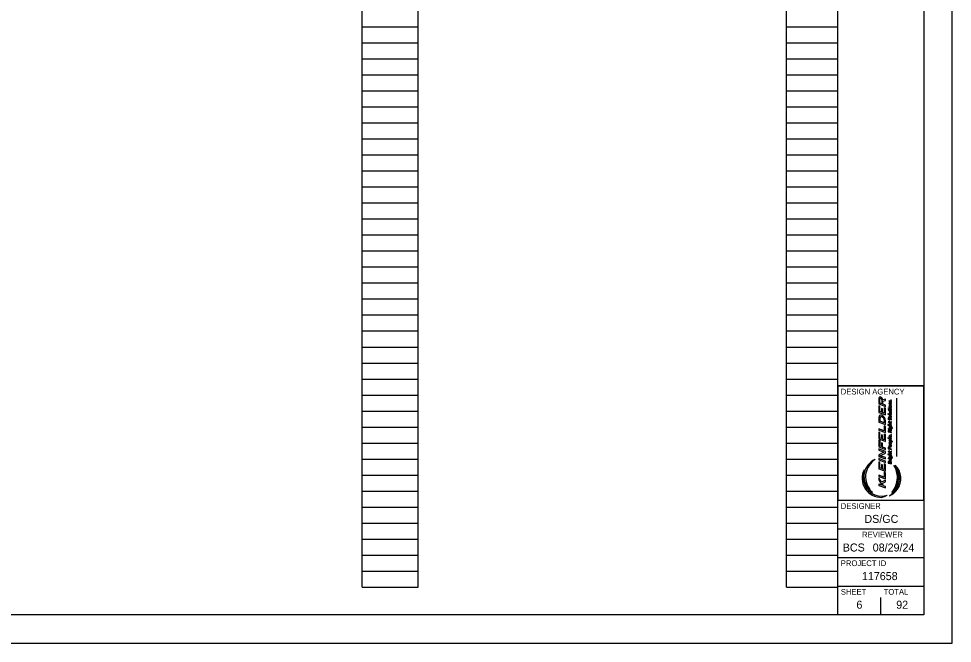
# Model space of a CAD drawing. Extents: x -9.5 to 34, y -6.8 to 28.4.
# Drawn here: x 17.67 to 34, y 0 to 10.92 of the extents above; entities that cross this region are included whole.
import ezdxf

# ---------------------------------------------------------------- set-up
doc = ezdxf.new("R2010")
doc.units = 0
for name, color, linetype in [('PV_P_Drive', 7, 'Continuous'), ('SH_Border', 7, 'Continuous'), ('SH_Cut_Line', 7, 'Continuous'), ('SH_Data', 7, 'Continuous'), ('SH_Text', 7, 'Continuous')]:
    doc.layers.add(name, color=color, linetype=linetype)

msp = doc.modelspace()

# ---------------------------------------------------------------- linework, layer by layer
at = {"layer": 'PV_P_Drive'}
for p, q in [((23.68, 0.98), (23.68, 21.14)), ((24.66, 0.98), (24.66, 21.14)), ((31.1, 0.98), (31.1, 21.14)), ((32, 0.98), (32, 21.14)), ((23.68, 10.78), (24.66, 10.78)), ((31.1, 10.78), (32, 10.78)), ((23.68, 10.5), (24.66, 10.5)), ((31.1, 10.5), (32, 10.5)), ((23.68, 10.22), (24.66, 10.22)), ((31.1, 10.22), (32, 10.22)), ((23.68, 9.94), (24.66, 9.94)), ((31.1, 9.94), (32, 9.94)), ((23.68, 9.66), (24.66, 9.66)), ((31.1, 9.66), (32, 9.66)), ((23.68, 9.38), (24.66, 9.38)), ((31.1, 9.38), (32, 9.38)), ((23.68, 9.1), (24.66, 9.1)), ((31.1, 9.1), (32, 9.1)), ((23.68, 8.82), (24.66, 8.82)), ((31.1, 8.82), (32, 8.82)), ((23.68, 8.54), (24.66, 8.54)), ((31.1, 8.54), (32, 8.54)), ((23.68, 8.26), (24.66, 8.26)), ((31.1, 8.26), (32, 8.26)), ((23.68, 7.98), (24.66, 7.98)), ((31.1, 7.98), (32, 7.98)), ((23.68, 7.7), (24.66, 7.7)), ((31.1, 7.7), (32, 7.7)), ((23.68, 7.42), (24.66, 7.42)), ((31.1, 7.42), (32, 7.42)), ((23.68, 7.14), (24.66, 7.14)), ((31.1, 7.14), (32, 7.14)), ((23.68, 6.86), (24.66, 6.86)), ((31.1, 6.86), (32, 6.86)), ((23.68, 6.58), (24.66, 6.58)), ((31.1, 6.58), (32, 6.58)), ((23.68, 6.3), (24.66, 6.3)), ((31.1, 6.3), (32, 6.3)), ((23.68, 6.02), (24.66, 6.02)), ((31.1, 6.02), (32, 6.02)), ((23.68, 5.74), (24.66, 5.74)), ((31.1, 5.74), (32, 5.74)), ((23.68, 5.46), (24.66, 5.46)), ((31.1, 5.46), (32, 5.46)), ((23.68, 5.18), (24.66, 5.18)), ((31.1, 5.18), (32, 5.18)), ((23.68, 4.9), (24.66, 4.9)), ((31.1, 4.9), (32, 4.9)), ((23.68, 4.62), (24.66, 4.62)), ((31.1, 4.62), (32, 4.62)), ((23.68, 4.34), (24.66, 4.34)), ((31.1, 4.34), (32, 4.34)), ((23.68, 4.06), (24.66, 4.06)), ((31.1, 4.06), (32, 4.06)), ((23.68, 3.78), (24.66, 3.78)), ((31.1, 3.78), (32, 3.78)), ((23.68, 3.5), (24.66, 3.5)), ((31.1, 3.5), (32, 3.5)), ((23.68, 3.22), (24.66, 3.22)), ((31.1, 3.22), (32, 3.22)), ((23.68, 2.94), (24.66, 2.94)), ((31.1, 2.94), (32, 2.94)), ((23.68, 2.66), (24.66, 2.66)), ((31.1, 2.66), (32, 2.66)), ((23.68, 2.38), (24.66, 2.38)), ((31.1, 2.38), (32, 2.38)), ((23.68, 2.1), (24.66, 2.1)), ((31.1, 2.1), (32, 2.1)), ((23.68, 1.82), (24.66, 1.82)), ((31.1, 1.82), (32, 1.82)), ((23.68, 1.54), (24.66, 1.54)), ((31.1, 1.54), (32, 1.54)), ((23.68, 1.26), (24.66, 1.26)), ((31.1, 1.26), (32, 1.26)), ((23.68, 0.98), (24.66, 0.98)), ((31.1, 0.98), (32, 0.98))]:
    msp.add_line(p, q, dxfattribs=at)
msp.add_lwpolyline([(32, 2.5), (33.5, 2.5), (33.5, 4.5), (32, 4.5)], close=True, dxfattribs=at)
at = {"layer": 'SH_Border'}
msp.add_lwpolyline([(0, 0), (34, 0), (34, 22), (0, 22)], close=True, dxfattribs=at)
at = {"layer": 'SH_Cut_Line'}
for p, q in [((32, 0.5), (32, 21.5)), ((32, 4.5), (33.5, 4.5)), ((32, 2.5), (33.5, 2.5)), ((32, 2), (33.5, 2)), ((32, 1.5), (33.5, 1.5)), ((32, 1), (33.5, 1))]:
    msp.add_line(p, q, dxfattribs=at)
msp.add_lwpolyline([(1.5, 21.5), (33.5, 21.5), (33.5, 0.5), (1.5, 0.5)], close=True, dxfattribs=at)
at = {"layer": 'SH_Data'}
for p, q in [((32.75, 3.5), (32.75, 3.5)), ((32.375, 0.675), (32.375, 0.675)), ((32.75, 0.5), (32.75, 0.8))]:
    msp.add_line(p, q, dxfattribs=at)
at = {"layer": 'SH_Text'}
for p, q in [((32.735, 4.201), (32.735, 4.271)), ((32.901, 4.239), (32.895, 4.241)), ((32.925, 4.077), (32.9, 4.082)), ((32.927, 4.212), (32.933, 4.21)), ((32.934, 4.086), (32.928, 4.087)), ((32.888, 3.94), (32.88, 3.942)), ((32.936, 3.789), (32.893, 3.798)), ((32.924, 3.905), (32.932, 3.903)), ((32.934, 3.873), (32.928, 3.875)), ((32.942, 3.755), (32.949, 3.753)), ((32.902, 3.709), (32.902, 3.699)), ((32.91, 3.626), (32.91, 3.606)), ((32.933, 3.627), (32.926, 3.629)), ((32.91, 3.463), (32.91, 3.442)), ((32.933, 3.464), (32.926, 3.465)), ((32.936, 3.273), (32.893, 3.282)), ((32.905, 3.41), (32.905, 3.403)), ((32.912, 3.402), (32.912, 3.412)), ((32.934, 3.358), (32.928, 3.359)), ((32.903, 3.161), (32.903, 3.152)), ((32.928, 3.157), (32.928, 3.147)), ((32.942, 3.239), (32.949, 3.237))]:
    msp.add_line(p, q, dxfattribs=at)
for points in [[(32.715, 4.286), (32.715, 4.187), (32.829, 4.143), (32.829, 4.165), (32.787, 4.181), (32.787, 4.232), (32.829, 4.243), (32.829, 4.269), (32.786, 4.259)], [(32.766, 4.257), (32.766, 4.189), (32.735, 4.201)], [(32.926, 4.255), (32.926, 4.247), (32.934, 4.245), (32.934, 4.253), (32.926, 4.255)], [(33.024, 4.283), (33.024, 3.267)], [(32.715, 4.154), (32.715, 4.035), (32.829, 3.992), (32.829, 4.111), (32.809, 4.119), (32.809, 4.023), (32.78, 4.034), (32.78, 4.099), (32.759, 4.107), (32.759, 4.042), (32.735, 4.051), (32.735, 4.147), (32.715, 4.154)], [(32.877, 4.114), (32.877, 4.106), (32.885, 4.104), (32.885, 4.113), (32.877, 4.114)], [(32.9, 4.082), (32.9, 4.093), (32.893, 4.094), (32.893, 4.083), (32.881, 4.086), (32.884, 4.078), (32.893, 4.076), (32.893, 4.067), (32.9, 4.065), (32.9, 4.074), (32.924, 4.069)], [(32.899, 4.179), (32.893, 4.18), (32.893, 4.173), (32.934, 4.164), (32.934, 4.172), (32.911, 4.177)], [(32.893, 4.111), (32.893, 4.103), (32.934, 4.094), (32.934, 4.102), (32.893, 4.111)], [(32.906, 4.199), (32.934, 4.193), (32.934, 4.201), (32.909, 4.207)], [(32.715, 3.948), (32.715, 3.867), (32.829, 3.824), (32.829, 3.897)], [(32.808, 3.906), (32.808, 3.855), (32.736, 3.882), (32.736, 3.942)], [(32.875, 4.013), (32.875, 4.005), (32.934, 3.993), (32.934, 4.001), (32.875, 4.013)], [(32.928, 4.044), (32.934, 4.043), (32.934, 4.05), (32.893, 4.059), (32.893, 4.051), (32.917, 4.046)], [(32.921, 4.024), (32.893, 4.03), (32.893, 4.022), (32.918, 4.017)], [(32.715, 3.752), (32.715, 3.728), (32.829, 3.685), (32.829, 3.793), (32.809, 3.801), (32.809, 3.717), (32.715, 3.752)], [(32.898, 3.818), (32.874, 3.823), (32.874, 3.815), (32.934, 3.802), (32.934, 3.81), (32.913, 3.815)], [(32.893, 3.882), (32.893, 3.871), (32.881, 3.874), (32.884, 3.865), (32.893, 3.863), (32.893, 3.854), (32.9, 3.853), (32.9, 3.862), (32.924, 3.857)], [(32.925, 3.864), (32.9, 3.87), (32.9, 3.881), (32.893, 3.882)], [(32.893, 3.798), (32.893, 3.79), (32.9, 3.789)], [(32.908, 3.836), (32.934, 3.831), (32.934, 3.839), (32.908, 3.844)], [(32.759, 3.644), (32.759, 3.579), (32.735, 3.588), (32.735, 3.683), (32.715, 3.691), (32.715, 3.572), (32.829, 3.529), (32.829, 3.648), (32.809, 3.656), (32.809, 3.56), (32.78, 3.571), (32.78, 3.636), (32.759, 3.644)], [(32.875, 3.595), (32.875, 3.587), (32.934, 3.574), (32.934, 3.582), (32.875, 3.595)], [(32.877, 3.753), (32.877, 3.745), (32.885, 3.743), (32.885, 3.751), (32.877, 3.753)], [(32.879, 3.716), (32.879, 3.696), (32.934, 3.684), (32.934, 3.692), (32.909, 3.698), (32.909, 3.705)], [(32.902, 3.699), (32.885, 3.703), (32.885, 3.711)], [(32.893, 3.749), (32.893, 3.741), (32.934, 3.732), (32.934, 3.741), (32.893, 3.749)], [(32.914, 3.711), (32.934, 3.716), (32.934, 3.724), (32.911, 3.717)], [(32.92, 3.605), (32.916, 3.605), (32.916, 3.634), (32.913, 3.634)], [(32.926, 3.65), (32.926, 3.642), (32.934, 3.64), (32.934, 3.648), (32.926, 3.65)], [(32.759, 3.504), (32.759, 3.439), (32.736, 3.448), (32.736, 3.544), (32.715, 3.552), (32.715, 3.433), (32.829, 3.389), (32.829, 3.413), (32.78, 3.431), (32.78, 3.497), (32.759, 3.504)], [(32.899, 3.538), (32.893, 3.539), (32.893, 3.532), (32.951, 3.52), (32.951, 3.528), (32.929, 3.533)], [(32.92, 3.441), (32.916, 3.441), (32.916, 3.47), (32.913, 3.471)], [(32.715, 3.295), (32.715, 3.267), (32.829, 3.223), (32.829, 3.247), (32.741, 3.28), (32.829, 3.327), (32.829, 3.355), (32.715, 3.399), (32.715, 3.375), (32.802, 3.341), (32.715, 3.295)], [(32.898, 3.302), (32.874, 3.307), (32.874, 3.299), (32.934, 3.286), (32.934, 3.294), (32.913, 3.299)], [(32.879, 3.418), (32.879, 3.4), (32.934, 3.389), (32.934, 3.397), (32.912, 3.402)], [(32.893, 3.366), (32.893, 3.355), (32.881, 3.358), (32.884, 3.349), (32.893, 3.348), (32.893, 3.338), (32.9, 3.337), (32.9, 3.346), (32.924, 3.341)], [(32.905, 3.403), (32.885, 3.407), (32.885, 3.414)], [(32.925, 3.348), (32.9, 3.354), (32.9, 3.365), (32.893, 3.366)], [(32.893, 3.282), (32.893, 3.274), (32.9, 3.273)], [(32.908, 3.321), (32.934, 3.315), (32.934, 3.323), (32.908, 3.328)], [(32.715, 3.229), (32.715, 3.206), (32.829, 3.162), (32.829, 3.185), (32.715, 3.229)], [(32.715, 3.172), (32.715, 3.053), (32.829, 3.009), (32.829, 3.128), (32.809, 3.136), (32.809, 3.041), (32.78, 3.052), (32.78, 3.116), (32.759, 3.124), (32.759, 3.059), (32.735, 3.068), (32.735, 3.164), (32.715, 3.172)], [(32.877, 3.237), (32.877, 3.229), (32.885, 3.227), (32.885, 3.235), (32.877, 3.237)], [(32.879, 3.168), (32.879, 3.149), (32.934, 3.137), (32.934, 3.16)], [(32.903, 3.152), (32.885, 3.156), (32.885, 3.164)], [(32.893, 3.233), (32.893, 3.225), (32.934, 3.216), (32.934, 3.225), (32.893, 3.233)], [(32.9, 3.215), (32.893, 3.216), (32.893, 3.209)], [(32.899, 3.2), (32.893, 3.201), (32.893, 3.193), (32.934, 3.185), (32.934, 3.192), (32.911, 3.197)], [(32.928, 3.147), (32.909, 3.151), (32.909, 3.16)], [(32.715, 2.941), (32.715, 2.917), (32.829, 2.874), (32.829, 2.982), (32.809, 2.99), (32.809, 2.906), (32.715, 2.941)], [(32.715, 2.895), (32.715, 2.859), (32.769, 2.765), (32.715, 2.785), (32.715, 2.761), (32.829, 2.718), (32.829, 2.742), (32.795, 2.755), (32.772, 2.794), (32.829, 2.824), (32.829, 2.853), (32.76, 2.816), (32.715, 2.895)]]:
    msp.add_lwpolyline(points, dxfattribs=at)
for centre, radius, start, end in [((32.738, 4.285), 0.0235, 105.8602, 175.9527), ((32.734, 4.272), 0.0359, 63.9111, 93.4134), ((32.746, 4.272), 0.0116, 120.9282, 182.8587), ((32.744, 4.27), 0.0128, 71.295, 106.2465), ((32.739, 4.256), 0.0278, 3.188, 69.9483), ((32.728, 4.249), 0.059, 10.1322, 68.6534), ((32.907, 4.193), 0.0143, 136.2913, 182.0825), ((32.908, 4.192), 0.0157, 176.9051, 236.2062), ((32.916, 4.231), 0.0237, 155.8068, 177.518), ((32.909, 4.23), 0.0164, 172.9331, 212.9177), ((32.913, 4.141), 0.0207, 134.8616, 186.3333), ((32.914, 4.14), 0.0218, 183.0085, 235.1138), ((32.904, 4.225), 0.0102, 205.2791, 253.4117), ((32.906, 4.191), 0.0157, 78.3727, 128.7252), ((32.908, 4.231), 0.0105, 131.8722, 213.0859), ((32.909, 4.192), 0.0107, 164.3628, 217.5642), ((32.908, 4.141), 0.00982, 114.8029, 183.3912), ((32.91, 4.14), 0.0115, 178.7964, 222.8298), ((32.905, 4.191), 0.00751, 82.4034, 156.5016), ((32.911, 4.135), 0.0236, 80.4774, 121.3769), ((32.904, 4.228), 0.00472, 212.4264, 286.081), ((32.916, 4.196), 0.0192, 214.0093, 253.9548), ((32.917, 4.147), 0.0212, 222.6118, 267.8201), ((32.904, 4.225), 0.0096, 252.4577, 305.4949), ((32.915, 4.14), 0.0225, 234.7204, 275.0527), ((32.911, 4.134), 0.0176, 73.9781, 113.6531), ((32.9, 4.234), 0.0117, 294.6007, 337.5251), ((32.899, 4.232), 0.018, 306.3564, 329.8219), ((32.924, 4.224), 0.0139, 114.5985, 155.8852), ((32.937, 4.21), 0.0248, 133.1465, 150.3389), ((32.913, 4.137), 0.0217, 48.9189, 86.1506), ((32.911, 4.131), 0.0201, 30.777, 75.0314), ((32.918, 4.138), 0.0124, 261.6619, 324.7522), ((32.919, 4.134), 0.0164, 263.7465, 315.576), ((32.923, 4.224), 0.013, 67.7239, 111.621), ((32.923, 4.225), 0.00487, 54.9774, 133.6656), ((32.921, 4.222), 0.0081, 0.828, 56.4407), ((32.914, 4.221), 0.0154, 324.4952, 5.8801), ((32.919, 4.223), 0.0157, 25.7964, 57.936), ((32.917, 4.139), 0.0181, 359.1065, 54.0048), ((32.917, 4.136), 0.0122, 333.802, 26.7946), ((32.918, 4.081), 0.012, 359.8271, 33.4272), ((32.916, 4.135), 0.0192, 318.3025, 9.3316), ((32.917, 4.222), 0.0183, 351.4651, 24.96), ((32.894, 4.224), 0.0413, 341.1844, 354.3531), ((32.914, 4.081), 0.0207, 339.7319, 13.8876), ((32.763, 3.948), 0.0481, 135.8191, 179.4263), ((32.749, 3.952), 0.0358, 73.1779, 125.9306), ((32.756, 3.942), 0.0203, 112.5545, 180.292), ((32.755, 3.943), 0.0192, 70.7496, 111.8258), ((32.736, 3.898), 0.0911, 25.2799, 75.3517), ((32.747, 3.901), 0.0624, 24.8644, 76.4065), ((32.763, 3.907), 0.0458, 358.9317, 26.1463), ((32.744, 3.896), 0.0851, 0.5101, 28.8607), ((32.902, 3.931), 0.0246, 153.0923, 182.7278), ((32.914, 3.931), 0.0359, 182.7278, 201.3007), ((32.894, 3.926), 0.0157, 207.7495, 253.8409), ((32.899, 3.93), 0.0144, 140.4782, 179.939), ((32.897, 3.929), 0.0124, 175.3728, 230.5265), ((32.893, 3.928), 0.00909, 239.5135, 284.896), ((32.913, 3.969), 0.0207, 134.8616, 186.3333), ((32.914, 3.967), 0.0218, 183.0085, 235.1138), ((32.888, 3.932), 0.0149, 299.565, 339.2556), ((32.908, 3.969), 0.00982, 114.8029, 183.3912), ((32.91, 3.968), 0.0115, 178.7964, 222.8298), ((32.911, 3.963), 0.0236, 80.4774, 121.3769), ((32.887, 3.931), 0.0238, 303.1236, 337.1341), ((32.917, 3.974), 0.0212, 222.6118, 267.8201), ((32.915, 3.968), 0.0225, 234.7204, 275.0527), ((32.921, 3.918), 0.0202, 112.5492, 156.2929), ((32.911, 3.961), 0.0176, 73.9781, 113.6531), ((32.919, 3.918), 0.011, 90.8577, 158.2517), ((32.918, 3.92), 0.018, 58.4507, 105.0331), ((32.913, 3.965), 0.0217, 48.9189, 86.1506), ((32.911, 3.959), 0.0201, 30.777, 75.0314), ((32.918, 3.966), 0.0124, 261.6619, 324.7522), ((32.911, 4.028), 0.0192, 34.0093, 73.9548), ((32.919, 3.962), 0.0164, 263.7465, 315.576), ((32.922, 4.032), 0.0157, 258.3727, 308.7252), ((32.918, 3.919), 0.0099, 7.9705, 84.8943), ((32.922, 4.032), 0.00751, 262.4034, 336.5016), ((32.926, 4.078), 0.00899, 258.837, 329.2244), ((32.909, 3.917), 0.0192, 321.116, 10.1848), ((32.926, 4.081), 0.00406, 265.2766, 359.8271), ((32.919, 4.032), 0.0107, 344.3628, 37.5642), ((32.915, 3.919), 0.0199, 358.5943, 53.7031), ((32.92, 4.031), 0.0157, 356.9051, 56.2062), ((32.917, 3.966), 0.0181, 359.1065, 54.0048), ((32.917, 3.964), 0.0122, 333.802, 26.7946), ((32.916, 3.963), 0.0192, 318.3025, 9.3316), ((32.921, 4.03), 0.0143, 316.2913, 2.0825), ((32.903, 3.918), 0.0327, 332.8538, 1.7076), ((32.893, 3.926), 0.0158, 256.3758, 294.8902), ((32.909, 3.83), 0.017, 145.2436, 189.7855), ((32.912, 3.776), 0.0195, 166.4234, 246.8498), ((32.905, 3.829), 0.0129, 185.2859, 235.9293), ((32.904, 3.778), 0.0113, 111.6426, 168.888), ((32.906, 3.83), 0.0141, 80.6828, 137.5266), ((32.907, 3.828), 0.00818, 136.5529, 210.7681), ((32.909, 3.777), 0.0102, 156.145, 220.58), ((32.909, 3.776), 0.0105, 93.2154, 153.4686), ((32.917, 3.835), 0.0202, 210.678, 259.5619), ((32.906, 3.829), 0.00748, 78.1668, 139.4713), ((32.917, 3.786), 0.0229, 224.9845, 280.2941), ((32.916, 3.782), 0.0268, 243.1201, 290.541), ((32.91, 3.764), 0.0226, 65.4895, 96.081), ((32.916, 3.773), 0.0125, 4.6127, 71.2311), ((32.92, 3.772), 0.00874, 280.0175, 10.7991), ((32.926, 3.866), 0.00899, 258.837, 329.2244), ((32.926, 3.868), 0.00406, 265.2766, 359.8271), ((32.919, 3.771), 0.0158, 297.2493, 349.812), ((32.918, 3.868), 0.012, 359.8271, 33.4272), ((32.919, 3.772), 0.0154, 347.3096, 45.7047), ((32.929, 3.764), 0.0181, 52.9431, 88.3704), ((32.914, 3.869), 0.0207, 339.7319, 13.8876), ((32.933, 3.771), 0.0178, 23.5672, 81.0788), ((32.93, 3.767), 0.0158, 15.8406, 51.2557), ((32.927, 3.767), 0.0194, 322.3021, 11.6769), ((32.921, 3.767), 0.0312, 334.3125, 21.7018), ((32.893, 3.714), 0.0143, 114.3537, 174.3612), ((32.895, 3.711), 0.00918, 126.0182, 180.1757), ((32.891, 3.712), 0.0163, 54.324, 105.2141), ((32.893, 3.708), 0.0111, 71.543, 108.457), ((32.905, 3.622), 0.0124, 112.1338, 170.4587), ((32.915, 3.619), 0.0226, 169.5031, 205.801), ((32.916, 3.62), 0.0231, 206.9109, 260.8013), ((32.891, 3.709), 0.0113, 2.8048, 63.3705), ((32.907, 3.618), 0.00858, 117.3851, 158.6637), ((32.91, 3.619), 0.0119, 168.1247, 206.2564), ((32.912, 3.619), 0.0135, 203.2444, 260.0416), ((32.89, 3.71), 0.0187, 16.6516, 54.9416), ((32.909, 3.609), 0.0257, 81.9878, 109.8531), ((32.907, 3.615), 0.012, 75.5066, 109.4211), ((32.913, 3.712), 0.00573, 112.0732, 152.0788), ((32.915, 3.705), 0.00539, 102.6271, 185.8955), ((32.917, 3.618), 0.0209, 255.6438, 310.1539), ((32.918, 3.617), 0.0122, 278.9982, 314.1507), ((32.892, 3.614), 0.0374, 10.3368, 23.7103), ((32.91, 3.618), 0.0187, 328.9592, 8.5627), ((32.916, 3.614), 0.0192, 319.8498, 2.5151), ((32.888, 3.615), 0.047, 359.6882, 15.2269), ((32.894, 3.417), 0.0158, 126.8786, 177.6793), ((32.893, 3.414), 0.0183, 67.3357, 118.1453), ((32.908, 3.552), 0.016, 128.4644, 186.7325), ((32.91, 3.552), 0.0179, 186.9887, 232.7091), ((32.913, 3.5), 0.0207, 134.8616, 186.3333), ((32.914, 3.499), 0.0218, 183.0085, 235.1138), ((32.905, 3.458), 0.0124, 112.1338, 170.4587), ((32.915, 3.456), 0.0226, 169.5031, 205.801), ((32.916, 3.456), 0.0231, 206.9109, 260.8013), ((32.907, 3.55), 0.00899, 131.5529, 215.9721), ((32.908, 3.501), 0.00982, 114.8029, 183.3912), ((32.91, 3.5), 0.0115, 178.7964, 222.8298), ((32.91, 3.54), 0.0268, 74.1204, 115.3732), ((32.911, 3.495), 0.0236, 80.4774, 121.3769), ((32.907, 3.455), 0.00858, 117.3851, 158.6637), ((32.91, 3.455), 0.0119, 168.1247, 206.2564), ((32.916, 3.554), 0.0182, 210.6491, 255.0946), ((32.912, 3.455), 0.0135, 203.2444, 260.0416), ((32.91, 3.547), 0.0133, 76.6402, 131.7242), ((32.917, 3.506), 0.0212, 222.6118, 267.8201), ((32.909, 3.445), 0.0257, 81.9878, 109.8531), ((32.893, 3.413), 0.0192, 355.6807, 65.6249), ((32.915, 3.5), 0.0225, 234.7204, 275.0527), ((32.907, 3.451), 0.012, 75.5066, 109.4211), ((32.911, 3.493), 0.0176, 73.9781, 113.6531), ((32.917, 3.552), 0.0167, 247.995, 291.3144), ((32.917, 3.454), 0.0209, 255.6438, 310.1539), ((32.911, 3.539), 0.0207, 43.01, 84.1033), ((32.913, 3.497), 0.0217, 48.9189, 86.1506), ((32.911, 3.491), 0.0201, 30.777, 75.0314), ((32.918, 3.497), 0.0124, 261.6619, 324.7522), ((32.914, 3.544), 0.0228, 23.9558, 80.548), ((32.919, 3.494), 0.0164, 263.7465, 315.576), ((32.918, 3.453), 0.0122, 278.9982, 314.1507), ((32.918, 3.546), 0.0114, 295.6576, 343.4617), ((32.919, 3.545), 0.0101, 346.7314, 48.3063), ((32.892, 3.45), 0.0374, 10.3368, 23.7103), ((32.91, 3.454), 0.0187, 328.9592, 8.5627), ((32.917, 3.498), 0.0181, 359.1065, 54.0048), ((32.917, 3.496), 0.0122, 333.802, 26.7946), ((32.917, 3.547), 0.0184, 309.5558, 17.4679), ((32.916, 3.495), 0.0192, 318.3025, 9.3316), ((32.916, 3.45), 0.0192, 319.8498, 2.5151), ((32.888, 3.451), 0.047, 359.6882, 15.2269), ((32.895, 3.415), 0.00934, 123.5007, 184.662), ((32.894, 3.412), 0.0119, 57.2999, 110.5503), ((32.909, 3.314), 0.017, 145.2436, 189.7855), ((32.905, 3.313), 0.0129, 185.2859, 235.9293), ((32.904, 3.262), 0.0113, 111.6426, 168.888), ((32.906, 3.314), 0.0141, 80.6828, 137.5266), ((32.907, 3.312), 0.00818, 136.5529, 210.7681), ((32.909, 3.26), 0.0105, 93.2154, 153.4686), ((32.89, 3.411), 0.0145, 357.8598, 47.6882), ((32.917, 3.319), 0.0202, 210.678, 259.5619), ((32.906, 3.313), 0.00748, 78.1668, 139.4713), ((32.91, 3.248), 0.0226, 65.4895, 96.081), ((32.916, 3.257), 0.0125, 4.6127, 71.2311), ((32.926, 3.35), 0.00899, 258.837, 329.2244), ((32.926, 3.352), 0.00406, 265.2766, 359.8271), ((32.918, 3.352), 0.012, 359.8271, 33.4272), ((32.919, 3.256), 0.0154, 347.3096, 45.7047), ((32.929, 3.249), 0.0181, 52.9431, 88.3704), ((32.914, 3.353), 0.0207, 339.7319, 13.8876), ((32.933, 3.255), 0.0178, 23.5672, 81.0788), ((32.792, 2.906), 0.34, 115.1143, 168.3777), ((32.871, 2.888), 0.394, 124.4536, 166.9641), ((32.893, 3.167), 0.0148, 118.8217, 177.6001), ((32.893, 3.165), 0.00845, 104.5669, 183.2204), ((32.891, 3.164), 0.0165, 47.423, 108.0377), ((32.893, 3.165), 0.0084, 40.2808, 100.5581), ((32.912, 3.26), 0.0195, 166.4234, 246.8498), ((32.907, 3.211), 0.0136, 188.2387, 237.9511), ((32.909, 3.261), 0.0102, 156.145, 220.58), ((32.909, 3.211), 0.00995, 158.8231, 202.4085), ((32.887, 3.16), 0.0155, 3.7446, 38.6277), ((32.917, 3.216), 0.0194, 205.713, 250.7037), ((32.917, 3.27), 0.0229, 224.9845, 280.2941), ((32.886, 3.166), 0.0195, 8.6642, 31.5112), ((32.916, 3.266), 0.0268, 243.1201, 290.541), ((32.917, 3.165), 0.0129, 99.5096, 160.7154), ((32.917, 3.161), 0.00818, 113.2405, 191.7775), ((32.917, 3.162), 0.00788, 58.3862, 113.2405), ((32.918, 3.165), 0.0131, 56.795, 103.6323), ((32.92, 3.256), 0.00874, 280.0175, 10.7991), ((32.914, 3.157), 0.0135, 1.8674, 60.8259), ((32.914, 3.159), 0.0207, 4.8421, 55.7541), ((32.919, 3.255), 0.0158, 297.2493, 349.812), ((32.93, 3.251), 0.0158, 15.8406, 51.2557), ((32.927, 3.251), 0.0194, 322.3021, 11.6769), ((32.921, 3.251), 0.0312, 334.3125, 21.7018), ((32.599, 2.884), 0.443, 1.2686, 30.3182), ((32.706, 2.894), 0.347, 356.3155, 37.8631), ((32.771, 2.881), 0.328, 325.1289, 45.2058), ((32.7, 2.891), 0.376, 357.0055, 36.4292), ((32.771, 2.881), 0.328, 325.1289, 45.2058), ((32.7, 2.891), 0.376, 357.0055, 36.4292), ((32.756, 2.885), 0.333, 153.0899, 211.3353), ((32.801, 2.913), 0.363, 160.2384, 179.8908), ((32.792, 2.92), 0.337, 170.6744, 236.0558), ((32.855, 2.915), 0.373, 170.3407, 217.7725), ((32.832, 2.928), 0.394, 182.1375, 213.7556), ((32.705, 2.894), 0.37, 301.6203, 356.4398), ((32.705, 2.894), 0.37, 301.6203, 356.4398), ((32.626, 2.909), 0.415, 319.4476, 357.9721), ((32.706, 2.894), 0.348, 312.6314, 356.3155), ((32.755, 2.881), 0.33, 210.9374, 272.3516), ((32.761, 2.887), 0.313, 214.7279, 288.5434), ((32.804, 2.875), 0.309, 217.7725, 229.547), ((32.768, 2.883), 0.331, 293.3176, 325.0704), ((32.768, 2.883), 0.331, 293.3176, 325.0704), ((32.719, 2.797), 0.25, 281.4129, 304.5262)]:
    msp.add_arc(centre, radius, start, end, dxfattribs=at)

# ---------------------------------------------------------------- texts
at = {"layer": 'SH_Data'}
for s, height, p in [('DESIGN AGENCY', 0.1, (32.05, 4.35)), ('DESIGNER', 0.1, (32.05, 2.35)), ('DS/GC', 0.14, (32.463, 2.105)), ('REVIEWER', 0.1, (32.422, 1.85)), ('BCS', 0.14, (32.084, 1.605)), ('08/29/24', 0.14, (32.608, 1.605)), ('PROJECT ID', 0.1, (32.05, 1.35)), ('117658', 0.14, (32.419, 1.105)), ('SHEET', 0.1, (32.05, 0.85)), ('TOTAL', 0.1, (32.8, 0.85)), ('6', 0.14, (32.323, 0.605)), ('92', 0.14, (33.019, 0.605))]:
    msp.add_text(s, height=height, dxfattribs=at).set_placement(p)

doc.saveas('drawing.dxf')
